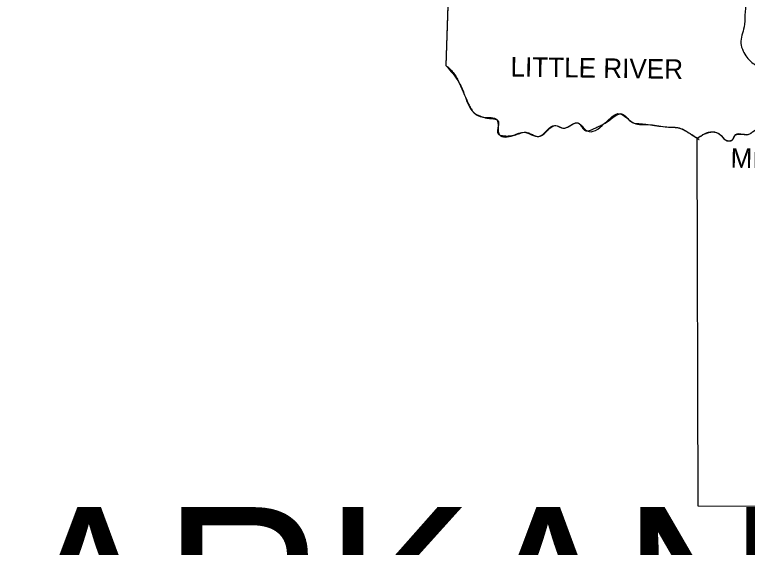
# Model space of a CAD drawing. Extents: x 3046 to 131673, y -8885 to 10756.
# Drawn here: x 62951 to 64530, y 4994 to 6142 of the extents above; entities that cross this region are included whole.
import ezdxf

# ---------------------------------------------------------------- set-up
doc = ezdxf.new("R2010")
doc.units = 0
for name, color, linetype in [('1', 7, 'Continuous'), ('2', 7, 'Continuous'), ('R_Annotation', 7, 'Continuous')]:
    doc.layers.add(name, color=color, linetype=linetype)

msp = doc.modelspace()

# ---------------------------------------------------------------- linework, layer by layer
at = {"layer": '1'}
for points in [[(63766.12484423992, 10312.988270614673), (63968.6550556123, 8686.876140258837), (63880.59844191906, 6032.458444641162)], [(64421.65741198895, 5874.934947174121), (64423.614225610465, 5083.403831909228), (68009.47521109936, 5077.533390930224)]]:
    msp.add_lwpolyline(points, dxfattribs=at)
for points in [[(64352.190527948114, 6825.946373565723), (64357.08256194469, 6796.594169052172), (64365.8882234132, 6771.155591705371), (64366.86663012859, 6751.587455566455), (64375.6722915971, 6722.2352509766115), (64375.6722915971, 6711.472775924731), (64378.607512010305, 6689.947825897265), (64374.69388469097, 6678.2069442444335), (64379.585918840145, 6654.7251806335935), (64378.607512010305, 6637.11385784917), (64378.607512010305, 6622.437755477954), (64379.585918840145, 6597.977585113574), (64387.41317324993, 6576.452635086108), (64395.24042777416, 6544.16521015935), (64400.13246199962, 6527.532294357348), (64407.95971652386, 6502.09371708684), (64412.851750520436, 6470.7846988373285), (64413.830157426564, 6447.302935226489), (64411.87334380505, 6425.777985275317), (64417.7437847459, 6401.317814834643), (64428.5062596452, 6376.857644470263), (64442.203955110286, 6353.375880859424), (64458.83687095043, 6326.9588968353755), (64470.57775275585, 6306.41235356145), (64485.25385512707, 6283.908996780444), (64496.99473693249, 6265.319267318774), (64514.606059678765, 6241.837503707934), (64522.433314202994, 6222.2693672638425), (64522.433314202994, 6194.873976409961), (64526.3469413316, 6169.435399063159), (64525.368534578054, 6141.061601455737), (64523.41172095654, 6115.623024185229), (64516.56287330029, 6080.400378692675), (64521.454907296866, 6063.767462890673), (64540.04463679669, 6039.307292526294), (64551.785518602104, 6032.458444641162), (64572.33206187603, 6028.544817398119), (64582.11613005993, 6014.847121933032), (64587.98657096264, 5994.300578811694), (64608.53311408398, 5987.451731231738), (64631.03647082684, 5985.49491757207), (64641.79894587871, 5973.75403576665), (64656.475048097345, 5958.099526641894), (64661.36708228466, 5950.272272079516)], [(63880.59844191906, 6032.458444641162), (63908.97223960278, 5995.2789855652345), (63920.7131214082, 5968.862001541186), (63937.34603740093, 5934.61776295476), (63961.806207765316, 5920.920067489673), (63990.18000544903, 5916.028033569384), (63996.050446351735, 5882.7622016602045), (64025.40265090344, 5881.783794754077), (64048.88441455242, 5888.632642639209), (64081.17183947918, 5879.826981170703), (64115.4160780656, 5903.308744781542), (64134.984214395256, 5897.438303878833), (64163.35801223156, 5909.179185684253), (64184.88296206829, 5891.567862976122), (64222.06242118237, 5907.222372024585), (64255.32825301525, 5928.747322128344), (64286.63727118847, 5908.200778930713), (64316.96788249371, 5905.2655584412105), (64353.1689346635, 5900.373524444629), (64381.54273249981, 5898.416710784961), (64406.98130961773, 5885.697422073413), (64425.57103927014, 5872.978133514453), (64421.65741198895, 5874.934947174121)], [(64421.65741198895, 5874.934947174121), (64455.90165057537, 5889.611049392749), (64470.57775275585, 5884.719015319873), (64483.2970414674, 5871.999726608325), (64497.97314368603, 5871.999726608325), (64505.80039821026, 5883.740608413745), (64520.47650058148, 5884.719015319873), (64532.2173822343, 5883.740608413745), (64544.936670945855, 5891.567862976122), (64555.69914588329, 5896.459897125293), (64570.37524825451, 5901.351931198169), (64581.1377231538, 5905.2655584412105), (64590.9217913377, 5916.028033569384), (64608.53311408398, 5924.833694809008), (64629.07965716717, 5931.682542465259), (64634.95009810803, 5941.466610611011), (64644.73416629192, 5945.380237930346), (64664.30230265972, 5944.401831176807), (64677.02159121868, 5950.272272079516), (64687.78406630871, 5945.380237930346), (64697.56813445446, 5938.531390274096), (64699.52494811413, 5913.092813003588), (64707.352202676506, 5899.395117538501), (64719.09308452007, 5874.934947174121), (64735.726000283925, 5862.215658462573), (64751.380509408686, 5849.496369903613), (64757.25095034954, 5841.669115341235), (64773.88386618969, 5826.993013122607), (64788.55996852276, 5822.100978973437), (64795.408816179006, 5811.338503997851), (64806.1712910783, 5785.899926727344), (64821.82580016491, 5763.396570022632)]]:
    msp.add_spline(points, degree=3, dxfattribs=at)
at = {"layer": 'R_Annotation'}
msp.add_lwpolyline([(63894.80040004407, 6460.56858172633), (63894.78975283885, 6460.247627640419), (63880.59844191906, 6032.458444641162)], dxfattribs=at)
for points in [[(63880.59844191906, 6032.458444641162), (63883.29938166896, 6030.414602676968), (63885.824189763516, 6028.338088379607), (63890.39037213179, 6024.083062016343), (63897.90372960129, 6015.137152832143), (63903.8578926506, 6005.55702478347), (63908.97223960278, 5995.2789855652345), (63920.7131214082, 5968.862001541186), (63928.48558504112, 5951.60309747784), (63932.65100420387, 5943.0645356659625), (63934.916217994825, 5938.828213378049), (63937.34603740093, 5934.61776295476), (63942.05956448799, 5929.502604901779), (63948.238171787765, 5926.016457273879), (63955.08575448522, 5923.406538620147), (63958.511628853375, 5922.194920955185), (63961.806207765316, 5920.920067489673), (63968.73386795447, 5919.115186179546), (63976.08010426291, 5918.447405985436), (63983.382841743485, 5917.792948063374), (63990.18000544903, 5916.028033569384), (63992.85839958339, 5913.525793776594), (63993.79252281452, 5909.523046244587), (63992.80530464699, 5899.07076390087), (63991.97304710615, 5888.780658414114), (63993.10087112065, 5884.980631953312), (63996.050446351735, 5882.7622016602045), (63999.62766935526, 5881.817135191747), (64003.28445551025, 5881.151732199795), (64010.73004958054, 5880.570741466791), (64018.17389317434, 5880.840879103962), (64025.40265090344, 5881.783794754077), (64031.27266973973, 5883.275230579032), (64037.14102347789, 5885.315713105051), (64043.01063184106, 5887.302448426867), (64048.88441455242, 5888.632642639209), (64052.91065213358, 5888.646689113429), (64056.94636939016, 5887.780235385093), (64065.03282102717, 5884.529825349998), (64073.11692565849, 5881.12940859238), (64079.16231568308, 5879.832964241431), (64081.17183947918, 5879.826981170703), (64083.60416534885, 5880.211609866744), (64090.31363802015, 5883.659419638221), (64098.439199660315, 5891.388372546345), (64106.49214085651, 5899.207070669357), (64110.78625893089, 5901.96045880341), (64115.4160780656, 5903.308744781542), (64120.24896545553, 5902.643557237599), (64125.174627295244, 5900.566358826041), (64130.11304860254, 5898.392743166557), (64134.984214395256, 5897.438303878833), (64138.595329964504, 5898.0050355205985), (64142.1952719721, 5899.380608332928), (64149.3471876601, 5903.45538289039), (64156.41106617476, 5907.456838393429), (64161.63381834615, 5909.082894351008), (64163.35801223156, 5909.179185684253), (64166.33733112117, 5908.273508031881), (64169.09234302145, 5906.020330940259), (64174.213088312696, 5899.4260557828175), (64179.28753302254, 5893.305514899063), (64181.9846691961, 5891.644505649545), (64184.88296206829, 5891.567862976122), (64203.613599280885, 5898.334242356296), (64213.12353287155, 5902.627254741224), (64222.06242118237, 5907.222372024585), (64230.3917553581, 5912.674856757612), (64238.7107368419, 5918.969171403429), (64247.022018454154, 5924.771323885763), (64251.17560081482, 5927.07096679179), (64253.25202245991, 5927.997477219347), (64255.32825301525, 5928.747322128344), (64263.04275161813, 5927.124417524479), (64270.66031548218, 5920.232740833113), (64278.43910265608, 5912.461718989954), (64286.63727118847, 5908.200778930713), (64293.84839821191, 5907.449400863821), (64301.482954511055, 5906.800998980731), (64309.27732197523, 5906.118681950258), (64316.96788249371, 5905.2655584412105), (64335.067976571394, 5902.814273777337), (64353.1689346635, 5900.373524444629), (64360.248966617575, 5899.82733947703), (64367.36533890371, 5899.664319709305), (64374.476958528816, 5899.366698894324), (64378.01814453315, 5899.005611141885), (64381.54273249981, 5898.416710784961), (64388.28419258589, 5896.253236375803), (64394.61068739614, 5893.036265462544), (64400.76284903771, 5889.329695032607), (64406.98130961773, 5885.697422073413), (64410.63965093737, 5883.605693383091), (64414.86918529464, 5881.001672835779), (64422.70489375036, 5875.762733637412)], [(64422.70489375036, 5875.762733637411), (64430.772422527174, 5881.300332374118), (64439.055965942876, 5885.515487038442), (64447.46316246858, 5888.316343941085), (64451.684267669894, 5889.1577064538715), (64455.90165057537, 5889.611049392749), (64459.55544959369, 5889.341318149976), (64463.254697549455, 5888.264884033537), (64466.9464475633, 5886.638524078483), (64470.57775275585, 5884.719015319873), (64474.22581250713, 5881.84193745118), (64477.19919592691, 5878.289693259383), (64480.04167993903, 5874.772287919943), (64483.2970414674, 5871.999726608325), (64490.611852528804, 5870.38422223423), (64494.539228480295, 5870.8442190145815), (64497.97314368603, 5871.999726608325), (64500.16966668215, 5874.5058688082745), (64501.58026906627, 5878.25179409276), (64503.14412239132, 5881.806906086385), (64505.80039821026, 5883.740608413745), (64509.467524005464, 5884.283980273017), (64513.13790549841, 5884.597624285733), (64516.808558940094, 5884.727362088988), (64520.47650058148, 5884.719015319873), (64523.41388130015, 5884.3910291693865), (64526.35180266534, 5883.812605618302), (64530.75319876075, 5883.479551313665), (64531.48552894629, 5883.578457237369), (64532.2173822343, 5883.740608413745), (64535.662701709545, 5885.222733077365), (64538.75523989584, 5887.350551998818), (64541.758671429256, 5889.630212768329), (64544.936670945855, 5891.567862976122), (64547.58843521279, 5892.860173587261), (64550.25058661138, 5894.153550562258), (64555.69914588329, 5896.459897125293), (64570.37524825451, 5901.351931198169), (64581.1377231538, 5905.2655584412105), (64583.983382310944, 5907.3571858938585), (64586.16158621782, 5910.381345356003), (64588.273875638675, 5913.538230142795), (64590.9217913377, 5916.028033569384), (64599.59016419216, 5920.722356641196), (64608.53311408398, 5924.833694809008), (64613.611445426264, 5926.688179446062), (64618.84536168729, 5928.177223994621), (64624.05978991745, 5929.706715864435), (64629.07965716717, 5931.682542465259), (64630.972642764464, 5933.590616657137), (64632.05419493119, 5936.356302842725), (64633.116088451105, 5939.2311258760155), (64634.95009810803, 5941.466610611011), (64637.28218501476, 5942.866234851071), (64639.690248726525, 5943.986147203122), (64644.73416629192, 5945.380237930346), (64649.6719964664, 5945.560966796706), (64654.7022717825, 5945.0118671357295), (64659.64052844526, 5944.402351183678), (64664.30230265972, 5944.401831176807), (64667.487259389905, 5945.663915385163), (64670.6651086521, 5947.879706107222), (64673.84137705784, 5949.824169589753), (64677.02159121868, 5950.272272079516), (64682.401482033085, 5948.295230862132), (64687.78406630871, 5945.380237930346), (64693.00957465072, 5942.386166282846), (64695.395566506, 5940.6674813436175), (64696.51144639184, 5939.664250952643), (64697.56813445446, 5938.531390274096), (64699.78376124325, 5932.707550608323), (64699.25950708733, 5926.034450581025), (64698.378770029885, 5919.250176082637), (64699.52494811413, 5913.092813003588), (64701.43373121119, 5909.655069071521), (64703.44064784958, 5906.245452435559), (64705.446528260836, 5902.835092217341), (64707.352202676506, 5899.395117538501), (64710.04227411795, 5893.147772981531), (64712.36978280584, 5886.65524926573), (64716.907163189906, 5877.550657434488), (64717.94364984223, 5876.207489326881), (64719.09308452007, 5874.934947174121), (64723.02543811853, 5871.414373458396), (64727.230172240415, 5868.298034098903), (64731.52459144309, 5865.32032909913), (64735.726000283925, 5862.215658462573), (64743.61651582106, 5855.938539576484), (64751.380509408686, 5849.496369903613), (64753.03185432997, 5847.718360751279), (64754.42166843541, 5845.70455215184), (64755.75851326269, 5843.629838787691), (64757.25095034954, 5841.669115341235), (64765.19999228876, 5833.874596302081), (64769.47753805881, 5830.341582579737), (64773.88386618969, 5826.993013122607), (64777.407294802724, 5825.487299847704), (64781.39752656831, 5824.851298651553), (64785.29995372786, 5824.0631461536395), (64787.0449256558, 5823.292680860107), (64788.55996852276, 5822.100978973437), (64792.42674540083, 5816.977172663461), (64795.408816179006, 5811.338503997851), (64798.2125810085, 5805.012819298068), (64800.780839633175, 5798.624648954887), (64803.3537052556, 5792.23376181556), (64806.1712910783, 5785.899926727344), (64809.27019658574, 5779.82862433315), (64812.74241923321, 5774.072396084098), (64816.84270507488, 5768.604093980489), (64819.20797983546, 5765.969431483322), (64821.82580016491, 5763.396570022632)]]:
    msp.add_spline(points, degree=3, dxfattribs=at)

# ---------------------------------------------------------------- texts
at = {"layer": '2'}
for s, height, rotation, p in [('LITTLE RIVER', 42.073449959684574, 359.1696833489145, (64019.532210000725, 6008.976681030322)), ('MILLER', 42.061709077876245, 359.1319472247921, (64494.059516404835, 5812.316910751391))]:
    msp.add_text(s, height=height, rotation=rotation, dxfattribs=at).set_placement(p)
msp.add_text('ARKANSAS HIGHWAY DISTRICT 3', height=360, dxfattribs=at).set_placement((62949.61558449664, 4720.468611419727))

doc.saveas('drawing.dxf')
